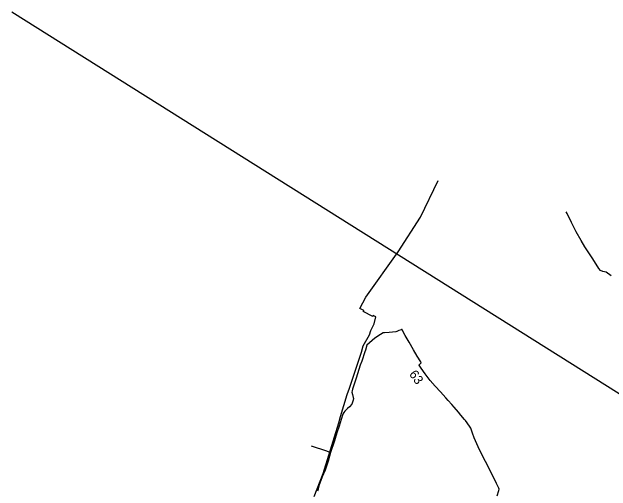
# Model space of a CAD drawing. Extents: x -444817 to -434929, y -1145681 to -1129851.
# Drawn here: x -442474 to -441954, y -1130412 to -1129996 of the extents above; entities that cross this region are included whole.
import ezdxf

# ---------------------------------------------------------------- set-up
doc = ezdxf.new("R2010")
doc.units = 0
for name, color, linetype in [('Vrstva 27', 7, 'Continuous'), ('Vrstva 30', 7, 'Continuous'), ('Vrstva 58', 7, 'Continuous'), ('Vrstva 59', 7, 'Continuous')]:
    doc.layers.add(name, color=color, linetype=linetype)

msp = doc.modelspace()

# ---------------------------------------------------------------- linework, layer by layer
at = {"layer": 'Vrstva 27'}
for points in [[(-441953.51, -1130224.92), (-441957.72, -1130221.82), (-441960.6, -1130221.32), (-441962.87, -1130220.33), (-441964.16, -1130218.55), (-441969.52, -1130210.23), (-441976.29, -1130199.95), (-441979.52, -1130194.33), (-441983.87, -1130186.68), (-441987.98, -1130178.65), (-441991.69, -1130170.94), (-441992.59, -1130169.31)], [(-442079.9, -1130350.8), (-442080.72, -1130349.82), (-442083.95, -1130345.93), (-442086.15, -1130343.29), (-442089.78, -1130339.15), (-442091.92, -1130336.64), (-442094.89, -1130333.36), (-442096.98, -1130330.89), (-442101.71, -1130325.85), (-442106.2, -1130320.87), (-442110.6, -1130315.89), (-442115.09, -1130309.99), (-442118.55, -1130305.24), (-442120.18, -1130302.7), (-442120.27, -1130302.2), (-442120.02, -1130301.92), (-442118.78, -1130300.96), (-442118.58, -1130300.51), (-442118.71, -1130299.84), (-442121.95, -1130294.69), (-442125.17, -1130289.28), (-442128.95, -1130282.75), (-442132.23, -1130276.81), (-442134.8, -1130272.02), (-442135.03, -1130271.7), (-442135.38, -1130271.66), (-442135.88, -1130271.82), (-442137.84, -1130272.55), (-442139.54, -1130273.39), (-442140.42, -1130273.63), (-442146.25, -1130274.26), (-442150.32, -1130274.44), (-442151.4, -1130274.61), (-442153.72, -1130275.93), (-442158.67, -1130279.06), (-442165.58, -1130285.16)], [(-442165.58, -1130285.16), (-442166.88, -1130289.45), (-442167.31, -1130290.89), (-442170.05, -1130299.02), (-442171.29, -1130302.68), (-442174.92, -1130314.01), (-442178.05, -1130323.3), (-442178.43, -1130324.8), (-442178.55, -1130326.11), (-442178.07, -1130328.19), (-442177.45, -1130330.69), (-442177.24, -1130331.45), (-442177.48, -1130332.9), (-442178.76, -1130336.47), (-442180.61, -1130338.69), (-442182.41, -1130340.24), (-442184.85, -1130342.63), (-442185.71, -1130343.7), (-442186.41, -1130345.27), (-442187.82, -1130349.86), (-442189.76, -1130355.67), (-442191.72, -1130361.5), (-442193.78, -1130368.29), (-442197.14, -1130378.53)], [(-442052.32, -1130416.01), (-442050.91, -1130411.56), (-442050.78, -1130410.39), (-442050.99, -1130409.38), (-442052.9, -1130405.32), (-442057.74, -1130395.86), (-442062.69, -1130386.17), (-442067.8, -1130376.28), (-442072.48, -1130365.85), (-442073.91, -1130361.78), (-442075.3, -1130357.4), (-442076.35, -1130355.52), (-442079.9, -1130350.8)], [(-442213.94, -1130372.53), (-442200.73, -1130377.15), (-442197.14, -1130378.53)], [(-442197.14, -1130378.53), (-442199.28, -1130385.84), (-442201.84, -1130393.88), (-442204.37, -1130399.52), (-442207.36, -1130407.29), (-442208.2, -1130411.49), (-442208.3, -1130411.94)]]:
    msp.add_lwpolyline(points, dxfattribs=at)
at = {"layer": 'Vrstva 58'}
for points in [[(-442168.69, -1130285.83), (-442163.33, -1130276.21), (-442162, -1130272.56), (-442159.36, -1130266.71), (-442157.94, -1130260.51), (-442159.56, -1130259.6), (-442160.01, -1130259.2), (-442160.51, -1130260.25), (-442168.79, -1130255.9), (-442168.24, -1130255.5), (-442168.29, -1130255.21), (-442171.63, -1130253.27), (-442166.44, -1130243.47), (-442138.31, -1130204.19), (-442119.03, -1130174.17), (-442103.65, -1130142.05)], [(-442211.44, -1130416.63), (-442203.63, -1130396.6), (-442190.03, -1130352.82), (-442188.43, -1130347.2), (-442182.55, -1130328.05), (-442180.53, -1130322.58), (-442170.21, -1130291.28), (-442168.69, -1130285.83)]]:
    msp.add_lwpolyline(points, dxfattribs=at)
at = {"layer": 'Vrstva 59'}
msp.add_lwpolyline([(-442473.66, -1129995.8), (-442052.58, -1130260.54), (-441235.62, -1130774.17), (-440949.15, -1130954.28)], dxfattribs=at)

# ---------------------------------------------------------------- texts
at = {"layer": 'Vrstva 30'}
msp.add_text('63', height=8, rotation=306.0704, dxfattribs=at).set_placement((-442129.31, -1130310.5))

doc.saveas('drawing.dxf')
